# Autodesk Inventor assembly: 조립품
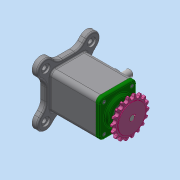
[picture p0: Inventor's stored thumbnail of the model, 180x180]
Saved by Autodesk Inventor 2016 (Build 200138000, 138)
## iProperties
Created: 2019-11
Part Number: 조립품
Material: 일반
Document SubType Name: Assembly
Designer: user
Author: user
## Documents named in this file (11)
- C:\Users\user\Desktop\491109V1005\조립품.iam
- C:\Users\user\Desktop\491109V1005\베어링 6203.ipt
- C:\Users\user\Desktop\491109V1005\본체.ipt
- C:\Users\user\Desktop\491109V1005\볼트 M4.ipt
- C:\Users\user\Desktop\491109V1005\부시.ipt
- C:\Users\user\Desktop\491109V1005\스프로킷.ipt
- C:\Users\user\Desktop\491109V1005\슬라이더.ipt
- C:\Users\user\Desktop\491109V1005\오일 실.ipt
- C:\Users\user\Desktop\491109V1005\커버.ipt
- C:\Users\user\Desktop\491109V1005\키 4 x 4 x 14.ipt
- C:\Users\user\Desktop\491109V1005\편심축.ipt
